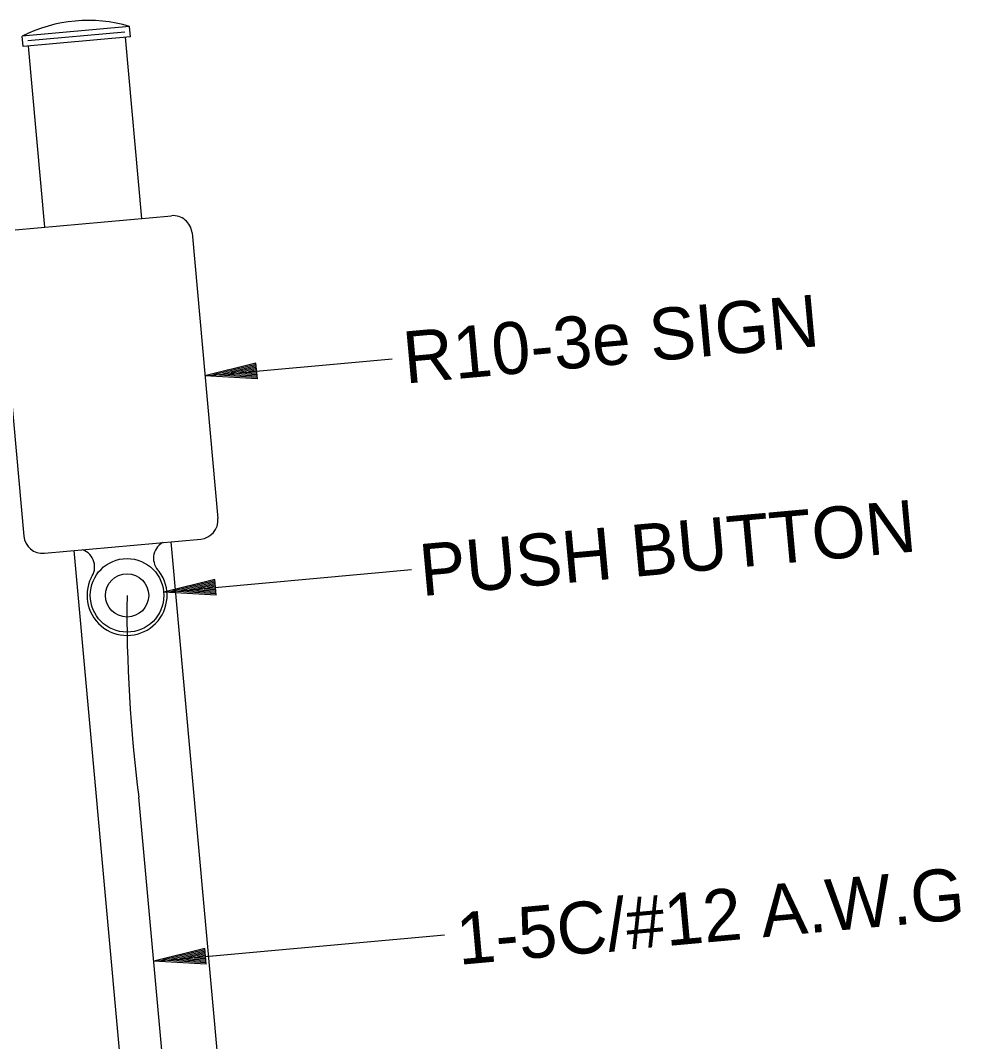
# Model space of a CAD drawing. Extents: x 1277218 to 1279252, y 196860 to 197529.
# Drawn here: x 1278336.3 to 1278419.3, y 197365.4 to 197455.6 of the extents above; entities that cross this region are included whole.
import ezdxf

# ---------------------------------------------------------------- set-up
doc = ezdxf.new("R2010")
doc.units = 0
doc.layers.add('R_Point Sym', color=7, linetype='Continuous')

msp = doc.modelspace()

# ---------------------------------------------------------------- linework, layer by layer
at = {"layer": 'R_Point Sym'}
for p, q in [((1278345.902, 197455.069), (1278336.417, 197454.21)), ((1278345.985, 197454.155), (1278345.902, 197455.069)), ((1278336.5, 197453.295), (1278336.417, 197454.21)), ((1278345.985, 197454.155), (1278336.5, 197453.295)), ((1278345.487, 197454.571), (1278336.916, 197453.794)), ((1278346.978, 197438.118), (1278345.528, 197454.113)), ((1278338.407, 197437.341), (1278336.957, 197453.337)), ((1278335.788, 197437.104), (1278349.596, 197438.355)), ((1278351.414, 197436.84), (1278353.701, 197411.603)), ((1278334.272, 197435.286), (1278336.559, 197410.05)), ((1278352.558, 197424.221), (1278369.109, 197425.721)), ((1278357.067, 197425.321), (1278352.558, 197424.221)), ((1278357.077, 197425.207), (1278353.321, 197424.291)), ((1278357.088, 197425.09), (1278354.107, 197424.362)), ((1278357.098, 197424.976), (1278354.868, 197424.431)), ((1278357.191, 197423.95), (1278357.067, 197425.321)), ((1278357.191, 197423.95), (1278352.558, 197424.221)), ((1278357.181, 197424.064), (1278353.321, 197424.291)), ((1278357.17, 197424.181), (1278354.107, 197424.362)), ((1278357.16, 197424.295), (1278354.868, 197424.431)), ((1278357.108, 197424.86), (1278355.643, 197424.501)), ((1278357.149, 197424.414), (1278355.643, 197424.501)), ((1278357.119, 197424.743), (1278356.407, 197424.57)), ((1278357.139, 197424.528), (1278356.407, 197424.57)), ((1278338.377, 197408.534), (1278352.185, 197409.785)), ((1278349.343, 197316.658), (1278340.996, 197408.771)), ((1278357.914, 197317.435), (1278349.567, 197409.548)), ((1278348.912, 197405.11), (1278370.797, 197407.094)), ((1278353.422, 197406.21), (1278348.912, 197405.11)), ((1278353.432, 197406.096), (1278349.676, 197405.18)), ((1278353.442, 197405.98), (1278350.462, 197405.251)), ((1278353.546, 197404.839), (1278353.422, 197406.21)), ((1278353.546, 197404.839), (1278348.912, 197405.11)), ((1278353.535, 197404.953), (1278349.676, 197405.18)), ((1278353.525, 197405.07), (1278350.462, 197405.251)), ((1278353.453, 197405.865), (1278351.223, 197405.32)), ((1278353.515, 197405.184), (1278351.223, 197405.32)), ((1278353.463, 197405.749), (1278351.998, 197405.39)), ((1278353.504, 197405.303), (1278351.998, 197405.39)), ((1278353.474, 197405.632), (1278352.761, 197405.459)), ((1278353.493, 197405.417), (1278352.761, 197405.459)), ((1278355.823, 197286.466), (1278346.715, 197386.983)), ((1278348.032, 197372.508), (1278373.72, 197374.836)), ((1278352.541, 197373.608), (1278348.032, 197372.508)), ((1278352.551, 197373.494), (1278348.795, 197372.578)), ((1278352.665, 197372.237), (1278352.541, 197373.608)), ((1278352.655, 197372.351), (1278348.795, 197372.578)), ((1278352.562, 197373.377), (1278349.581, 197372.649)), ((1278352.644, 197372.468), (1278349.581, 197372.649)), ((1278352.572, 197373.263), (1278350.342, 197372.718)), ((1278352.634, 197372.582), (1278350.342, 197372.718)), ((1278352.582, 197373.147), (1278351.117, 197372.788)), ((1278352.623, 197372.701), (1278351.117, 197372.788)), ((1278352.593, 197373.03), (1278351.881, 197372.857)), ((1278352.613, 197372.815), (1278351.881, 197372.857)), ((1278352.665, 197372.237), (1278348.032, 197372.508))]:
    msp.add_line(p, q, dxfattribs=at)
for radius in [3.251, 1.912]:
    msp.add_circle((1278345.675, 197404.817), radius, dxfattribs=at)
for centre, radius, start, end in [((1278342.233, 197442.795), 12.811, 73.35563, 117.00015), ((1278349.748, 197436.689), 1.673, 5.17789, 95.17789), ((1278352.034, 197411.452), 1.673, 275.17789, 5.17789), ((1278338.226, 197410.201), 1.673, 185.17789, 275.17789), ((1278341.207, 197407.331), 1.606, 323.37511, 69.98231), ((1278349.617, 197408.093), 1.606, 120.37348, 226.98068), ((1278345.675, 197404.817), 3.538, 153.91813, 36.43765), ((1278472.619, 197403.273), 126.954, 179.30296, 187.37182)]:
    msp.add_arc(centre, radius, start, end, dxfattribs=at)

# ---------------------------------------------------------------- texts
for s, p in [('R10-3e SIGN', (1278370.277, 197423.521)), ('PUSH BUTTON', (1278371.725, 197404.745)), ('1-5C/#12 A.W.G', (1278375, 197372.172))]:
    msp.add_text(s, height=4.58993, rotation=5.17789, dxfattribs=at).set_placement(p)

doc.saveas('drawing.dxf')
